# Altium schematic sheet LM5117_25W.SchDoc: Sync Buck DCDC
size 431 x 279 mm; Engineer: Yutao Wang (Steven); Organization: TESLA Motors, INC; Address1: 3500 Deer Creek Road; Address2: Palo Alto, CA; Address4: U.S.A.; SheetNumber: 5; SheetTotal: 7
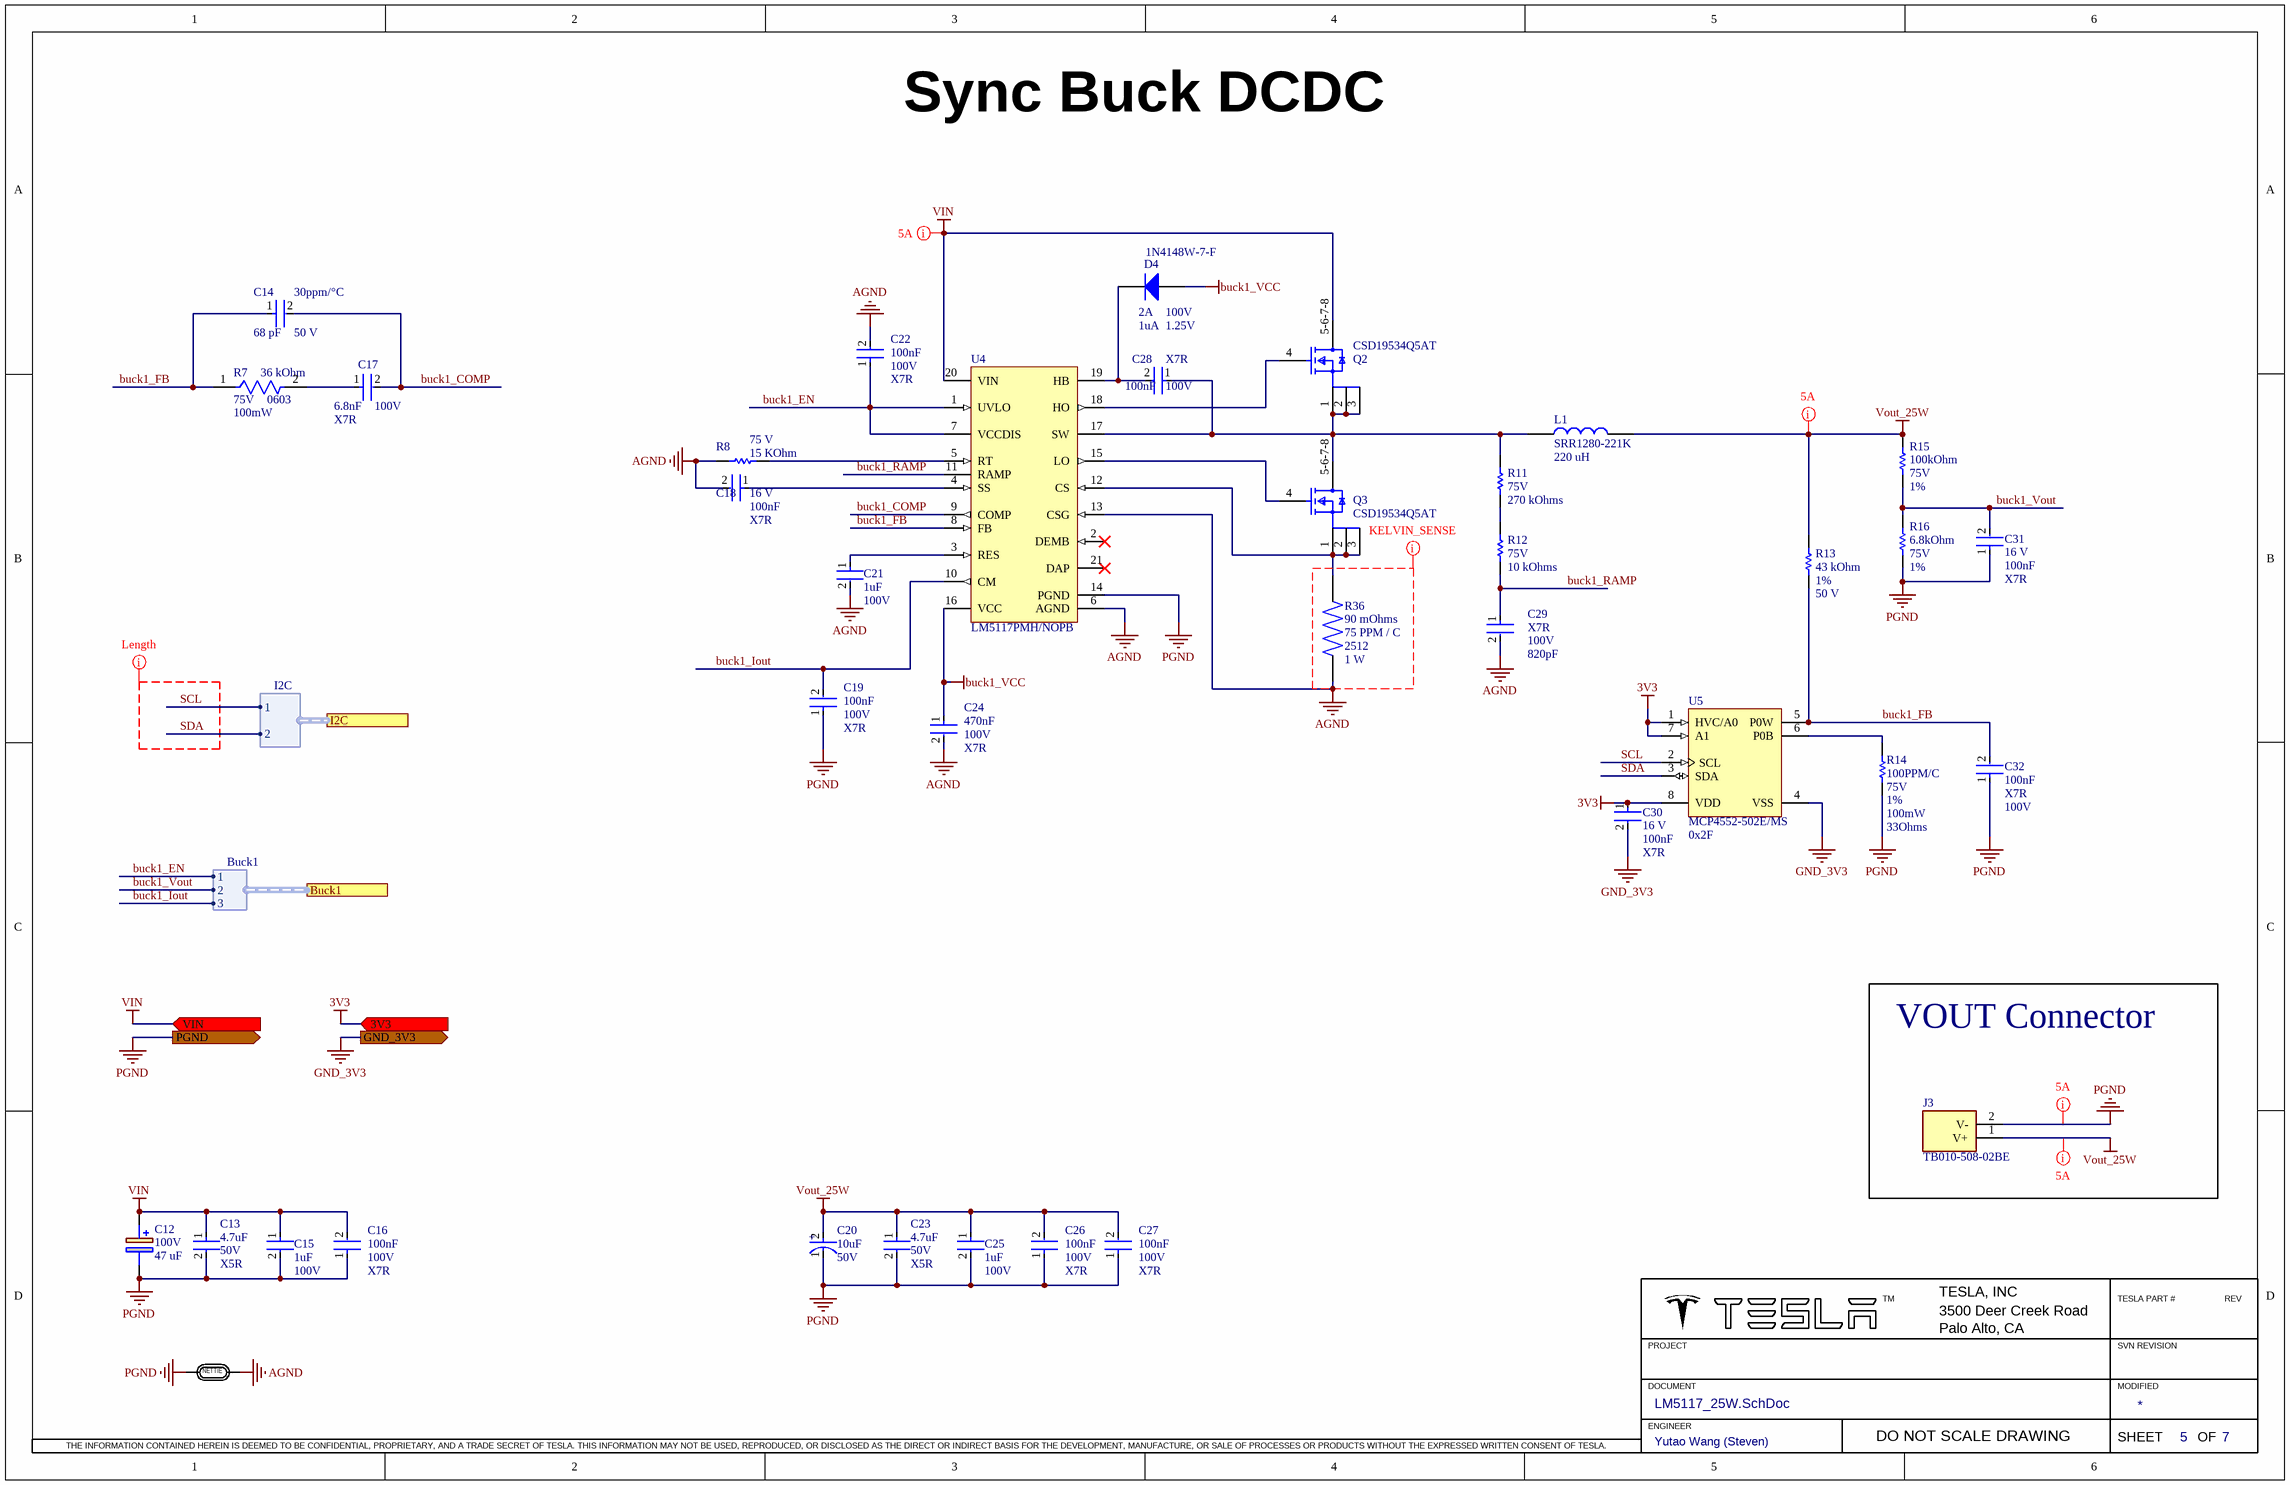
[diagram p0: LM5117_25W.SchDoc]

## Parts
C12  Voltage: 100V  Capacitance: 47 uF  [EDH476M100A9PAA]  (hidden comment: EDH476M100A9PAA)
C13  Voltage Rating (DC): 50V  Capacitance: 4.7uF  Dielectric: X5R  [FP-GRM21B-0_15-IPC_C]  (hidden comment: GRM21BR61H475ME51L)
C14  Voltage Rating: 50 V  Temperature Coefficient: 30ppm/°C  Capacitance: 68 pF  [FP-C0805C-DN-MFG]  (hidden comment: C0805C680J5GAC)
C15  Capacitance: 1uF  Voltage: 100V  [FP-C2012-125-0_2-IPC_A]  (hidden comment: C2012X7S2A105K125AB)
C16  Capacitance: 100nF  Dielectric: X7R  Voltage Rating (DC): 100V  [FP-CC1206-0_3-1_45-IPC_C]  (hidden comment: CC1206KKX7R0BB104)
C17  Voltage Rating: 100V  Capacitance: 6.8nF  Dielectric: X7R  [FP-GCM188-0_1-IPC_C]  (hidden comment: GCM188R72A682KA37D)
C18  Voltage Rating: 16 V  Capacitance: 100nF  Temperature Characteristic: X7R  [FP-C0402-BB-MFG]  (hidden comment: C0402C104K4RACTU)
C19  Capacitance: 100nF  Dielectric: X7R  Voltage Rating (DC): 100V  [FP-CC1206-0_3-1_45-IPC_C]  (hidden comment: CC1206KKX7R0BB104)
C20  Voltage: 50V  Capacitance: 10uF  [FP-FKD-MFG]  (hidden comment: EEE-FK1H100P)
C21  Capacitance: 1uF  Voltage: 100V  [FP-C2012-125-0_2-IPC_A]  (hidden comment: C2012X7S2A105K125AB)
C22  Capacitance: 100nF  Dielectric: X7R  Voltage Rating (DC): 100V  [FP-CC1206-0_3-1_45-IPC_C]  (hidden comment: CC1206KKX7R0BB104)
C23  Voltage Rating (DC): 50V  Capacitance: 4.7uF  Dielectric: X5R  [FP-GRM21B-0_15-IPC_C]  (hidden comment: GRM21BR61H475ME51L)
C24  Capacitance: 470nF  Voltage Rating (DC): 100V  Dielectric: X7R  [FP-GRM21B-0_15-IPC_A]  (hidden comment: GRM21BR72A474MA73L)
C25  Capacitance: 1uF  Voltage: 100V  [FP-C2012-125-0_2-IPC_A]  (hidden comment: C2012X7S2A105K125AB)
C26  Capacitance: 100nF  Dielectric: X7R  Voltage Rating (DC): 100V  [FP-CC1206-0_3-1_45-IPC_C]  (hidden comment: CC1206KKX7R0BB104)
C27  Capacitance: 100nF  Dielectric: X7R  Voltage Rating (DC): 100V  [FP-CC1206-0_3-1_45-IPC_C]  (hidden comment: CC1206KKX7R0BB104)
C28  Capacitance: 100nF  Dielectric: X7R  Voltage Rating (DC): 100V  [FP-CC1206-0_3-1_45-IPC_C]  (hidden comment: CC1206KKX7R0BB104)
C29  Capacitance: 820pF  Voltage: 100V  Grade: X7R  [FP-GCM155-0_05-IPC_A]  (hidden comment: GCM155R72A821KA37J)
C30  Voltage Rating: 16 V  Capacitance: 100nF  Temperature Characteristic: X7R  [FP-C0402-BB-MFG]  (hidden comment: C0402C104K4RACTU)
C31  Voltage Rating: 16 V  Capacitance: 100nF  Temperature Characteristic: X7R  [FP-C0402-BB-MFG]  (hidden comment: C0402C104K4RACTU)
C32  Capacitance: 100nF  Dielectric: X7R  Voltage Rating (DC): 100V  [FP-CC1206-0_3-1_45-IPC_C]  (hidden comment: CC1206KKX7R0BB104)
D4  1N4148W-7-F  Max Surge Current: 2A  Peak Reverse Voltage: 100V  Ir - Reverse Current: 1uA  Vf - Forward Voltage: 1.25V  [DIOD-SOD123-2_V]
J3  TB010-508-02BE  [CUI_TB010-508-02BE]
L1  SRR1280-221K  Inductance: 220 uH  [SRR1280-221K]
NT2  BOARD FEATURE  [NETTIE-0.5X0.5X0.4]  (value not drawn)  (net tie, no BOM)
Q2  CSD19534Q5AT  [FP-DQJ0008A-MFG]
Q3  CSD19534Q5AT  [FP-DQJ0008A-MFG]
R7  Voltage Rating: 75V  Max Power Dissipation: 100mW  Case Code (Imperial): 0603  Resistance: 36 kOhm  [FP-RC0603-0_55-IPC_C]  (hidden comment: RC0603FR-0736KL)
R8  Resistance: 15 KOhm  Voltage: 75 V  [RESC1608X55X25LL10T15]  (hidden comment: RC0603FR-0715KL)
R11  Voltage: 75V  Resistance: 270 kOhms  [RESC1608X55X25ML10T15]  (hidden comment: RC0603JR-07270KL)
R12  Voltage: 75V  Resistance: 10 kOhms  [RESC1608X55X25ML10T15]  (hidden comment: RC0603JR-1310KL)
R13  Resistance: 43 kOhm  Tolerence: 1%  Voltage: 50 V  [RESC1005X40X25NL05T10]  (hidden comment: RC0402FR-0743KL)
R14  Temperature Coefficient: 100PPM/C  Voltage Rating: 75V  Tolerance: 1%  Power Rating: 100mW  Resistance: 33Ohms  [RESC1608X55X25LL10T15]  (hidden comment: RC0603FR-0733RL)
R15  Resistance: 100kOhm  Voltage: 75V  Tolerence: 1%  [RESC1608X55X30ML15T15]  (hidden comment: ERJ-3EKF1003V)
R16  Voltage: 75V  Resistance: 6.8kOhm  Tolerence: 1%  [RESC1609X55X30NL15T15]  (hidden comment: ERJ-3EKF6801V)
R36  Resistance: 90 mOhms  PPM: 75 PPM / C  Size: 2512  Power: 1 W  [WSL2512R0900FEA]  (hidden comment: WSL2512R0900FEA)
U4  LM5117PMH/NOPB  [PWP0020A_N]
U5  MCP4552-502E/MS  [MSOP-MS8_N]

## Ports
3V3 (in), Buck1 (harness Buck1), GND_3V3 (out), I2C (harness I2C), PGND (out), VIN (in)

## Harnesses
I2C: 1, 2
Buck1: 1, 3, 2

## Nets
3V3: C30.1 U5.1(HVC/A0) U5.7(A1) U5.8(VDD) ; port 3V3
AGND: C18.2 C21.2 C22.2 C24.2 C29.2 NT2.1(C1) R8.1 R36.1 U4.6(AGND) U4.13(CSG)
buck1_VCC: C24.1 D4.1(A) U4.16(VCC)
GND_3V3: C30.2 U5.4(VSS) ; port GND_3V3
PGND: C12.2(-) C13.2 C15.2 C16.1 C19.1 C20.1(C) C23.2 C25.2 C26.1 C27.1 C31.1 C32.1 J3.2(V-) NT2.2(C2) R14.2 R16.1 U4.14(PGND) ; port PGND
VIN: C12.1(+) C13.1 C15.1 C16.2 Q2.5-6-7-8(D) U4.20(VIN) ; port VIN
Vout_25W: C20.2(A) C23.1 C25.1 C26.2 C27.2 J3.1(V+) L1.2 R13.2 R15.2
buck1_COMP: C14.2 C17.2 U4.9(COMP)
buck1_EN: C22.1 U4.1(UVLO) U4.7(VCCDIS) ; port Buck1.1
buck1_FB: C14.1 C32.2 R7.1 R13.1 U4.8(FB) U5.5(P0W)
buck1_Iout: C19.2 U4.10(CM) ; port Buck1.3
buck1_RAMP: C29.1 R12.1 U4.11(RAMP)
buck1_Vout: C31.2 R15.1 R16.2 ; port Buck1.2
SCL: U5.2(SCL) ; port I2C.1
SDA: U5.3(SDA) ; port I2C.2
NetC17_1: C17.1 R7.2
NetC18_1: C18.1 U4.4(SS)
NetC21_1: C21.1 U4.3(RES)
NetC28_1: C28.1 L1.1 Q2.1(S) Q2.2(S) Q2.3(S) Q3.5-6-7-8(D) R11.2 U4.17(SW)
NetC28_2: C28.2 D4.2(K) U4.19(HB)
NetQ2_4: Q2.4(G) U4.18(HO)
NetQ3_1: Q3.1(S) Q3.2(S) Q3.3(S) R36.2 U4.12(CS)
NetQ3_4: Q3.4(G) U4.15(LO)
NetR8_2: R8.2 U4.5(RT)
NetR11_1: R11.1 R12.2
NetR14_1: R14.1 U5.6(P0B)

Not connected (* = marked no-connect by the designer): U4 2(DEMB)* 21(DAP)*

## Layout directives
mark named 5A: PGND, VIN, Vout_25W
net class Length: (no net found under the mark)
mark named KELVIN_SENSE: AGND

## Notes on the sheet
- (near U5) 0x2F
- VOUT Connector

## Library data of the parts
C12 = EDH476M100A9PAA: EDH, Aluminum, Aluminum Electrolytic, 47 uF, 20%, 100 VDC, -40/+105C, 105C, -40C, 105C, 2,000 Hrs, 18 % , 0.17, 47 uA, 2, 3, 10mm, 10.2mm, 500; Manufacturer_Name: KEMET; Geometry.Height: 10.5mm
C13 C23 = CMP-06035-037765-1: Chip Multilayer Ceramic Capacitors for General Purpose, 0805, 4.7uF, X5R, 15%, 20%, 50V
C14 = CMP-03020-020862-1: C0805 68 pF C0G 30ppm/°C 5.00% 50 V; Manufacturer: KEMET; Value: 68 pF; Material: Ceramic; Tolerance: 0.05
C15 C21 C25 = CMP-2000-05454-2: Multilayer Ceramic Capacitors 1μF ±10% 100V X7S SMD 0805
C16 C19 C22 C26-C28 C32 = CMP-03422-001499-1: CAP CER 0.1UF 100V X7R 1206; Dielectric Material: Ceramic; Tolerance: 10%
C17 = CMP-2006-02398-2: Ceramic Capacitor for Automotive 6.8nF  ±10% 100VDC X7R 0603 Paper T/R
C18 C30 C31 = CMP-2008-02108-2: CAP CER 0.1UF 16V X7R 0402; Manufacturer: Kemet; Value: 0.10 μF; Tolerance: 0.1; Material: Ceramic; Temperature Coefficient: 15%
C20 = CMP-2000-06207-2: CAP ALUM 10UF 20% 50V SMD; Impedance: 880mR; Ripple Current: 165mA; Polarity: Polar; Leakage Current: 3uA; Lead Diameter: 0.65mm; Life (Hours): 2000Hour
C24 = CMP-06035-021373-1: Chip Multilayer Ceramic Capacitors for General Purpose, 0805, 0.47uF, X7R, 15%, 20%, 100V
C29 = CMP-06035-060413-1: Ceramic Capacitor for Automotive 820pF ±10% 100VDC X7R 0402 Paper T/R
D4 = CMP-2000-04932-2: Fast Switching Diode, 100 V, 0.15 A, -65 to 150 degC, 2-Pin?SOD123, RoHS, Tape and Reel; Recovery Time: 4ns; Brand: DiodesIncorporated; Unit Weight: 0.000353oz; Configuration: Single; If - Forward Current: 0.15A
J3 = TB010-508-02BE: 2~24 Poles, Screw Type, Horizontal, 5.08 Pitch, 26~12 (AWG), Terminal Block Connector; MF: CUI Devices
L1 = SRR1280-221K: Bourns SRR1280 Series Shielded Wire-wound SMD Inductor with a Ferrite Core, 220 uH +/-10% Wire-Wound 1.6A Idc Q:24; Geometry.Height: 8mm
NT2 = CMP-01115-6: NET TIE 0.5 x 0.5 mm, 0.4mm GAP; Manufacturer PartNo: NONE - BOARD FEATURE; Manufacturer: TESLA; AEC-Q: YES; Level: 1; Selective Soldering: NO; Pressfit: NO; Layout Notes: NET TIE
Q2 Q3 = CMP-04962-000018-1: MOSFET N-CH 100V 50 8SON; Manufacturer: Texas Instruments; Reverse Recovery Time: 53ns; Turn Off Delay Time: 20ns; Gate To Source Voltage: 20V; Turn On Delay Time: 9ns; Depletion Mode: False; Threshold Vgs Max: 3.4V; Pulse Drain Current: 137A; Number Of N Channels: 1; Input Capacitace At Vds: 1290pF @ 50V; Max Junction Temp: +150°C; Power Dissipation: 3.2W; Max Forward Diode Voltage: 1V; Continuous Drain Current: 10A; Drain To Source Resistance: 12.6mΩ; Threshold Vgs Min: 2.4V; Transconductance: 47S; Gate Charge At Vgs: 17nC @ 10V; Reverse Recovery Charge: 134nC; Typ Forward Diode Voltage: 0.8V; Rthja Max: 50°C/W
R7 = CMP-03412-037824-1: RES 36K OHM 1% 1/10W 0603; Temperature Coefficient: 100ppm/°C; Voltage Rating (DC): 50V
R8 = CMP-1659-00032-1: Chip Resistor, 15 KOhm, +/- 1%, 0.1 W, -55 to 155 degC, 0603 (1608 Metric), RoHS, Tape and Reel
R11 = CMP-2000-04314-1: Thick Film Resistors - SMD 270 kOhms 100 mW 0603 5%; Manufacturer: Yageo; Part Number: RC0603JR-1310KL
R12 = CMP-2000-04314-1: Thick Film Resistors - SMD 10 kOhms 100-200 mW 0603 5%; Manufacturer: Yageo
R13 = CMP-1011-00694-2: Thick Film Resistors - SMD 43 kOhms 62.5mW 0402 1%; Manufacturer: Yageo / Phycomp
R14 = CMP-2000-06939-1: Chip Resistor, 33 Ohm, +/- 1%, 0.1 W, -55 to 155 degC, 0603 (1608 Metric), RoHS, Tape and Reel; Unit Weight: 0.000071oz; Brand: Yageo
R15 = CMP-2000-00182-1: Thick Film Resistors - SMD 0603 100Kohms 1% AEC-Q200; Manufacturer: Panasonic
R16 = CMP-1012-00604-3: Chip Resistor, 6.8 KOhm, +/- 1%, 0.1 W, -55 to 155 degC, 0603 (1608 Metric), RoHS, Tape and Reel; Manufacturer PartNo: ERJ-3EKF6800V
R36 = WSL2512R0900FEA: SMD 1watt 90 mOhms 1%
U4 = CMP-0069-02227-2: Wide Input Range Synchronous Buck Controller with Analog Current Monitor, 20-pin TSSOP-EP, 73 Rail; Manufacturer: Texas Instruments; CompType: Switcher; High-Reliability: Y; PackageTopMarking: NSUZXYTT*LM5117*PMH
U5 = CMP-0188-00827-2: 8-Bit Single I2C Digital POT with Volatile Memory, 8-pin MSOP, Extended Temperature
